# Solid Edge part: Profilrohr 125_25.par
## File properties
Author: ahadarics
Last saved by: ahadarics
Revision: 77
Sűrűség: 0,000 kg/m^3
Pontosság: 0,990
Username: ahadarics
Dokumentum tartalom típus: 0
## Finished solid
Body 1: solid body, 175 faces, 518 edges, 344 vertices.
  Faces by surface: cylinder 107, plane 68
  Edges by curve: line 304, circle 214
Bounding box of the edges (mm): 131.500 x 131.500 x 91.000, from (-65.75, -65.75, -25.5) to (65.75, 65.75, 65.5).
Cylindrical faces by radius (mm): R0.1 x16, R0.2 x32, R0.5 x24, R1.5 x8, R2 x2, R5.275 x8, R8 x4, R8.25 x4, R62.5 x1, R65.5 x8
Planar faces by outward normal: +x 4, +y 6, +z 1, -x 4, -y 4, -z 1, oblique 48
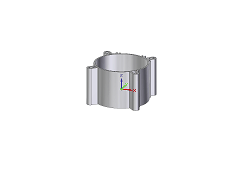
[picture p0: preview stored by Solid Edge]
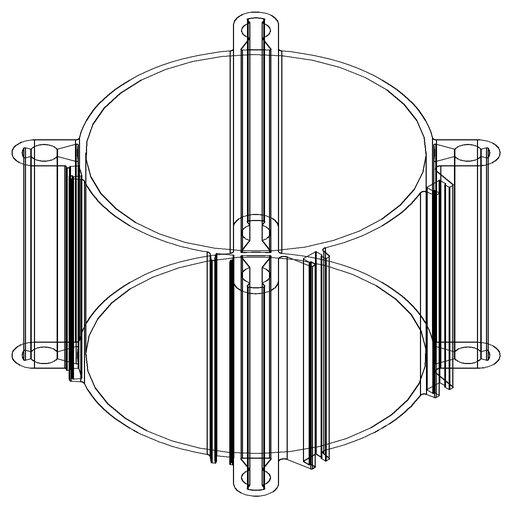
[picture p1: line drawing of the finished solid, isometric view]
